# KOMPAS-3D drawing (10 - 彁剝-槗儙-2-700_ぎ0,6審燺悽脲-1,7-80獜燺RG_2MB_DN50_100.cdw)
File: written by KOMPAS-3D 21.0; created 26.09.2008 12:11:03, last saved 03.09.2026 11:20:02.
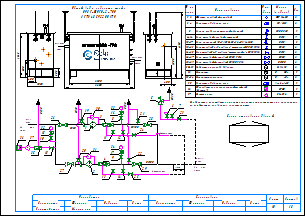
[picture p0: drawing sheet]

Sheets 1-2: A3, landscape

Document properties: Наименование: Макро:21; Автор: RaskoAdmin; Форматы листов документа: 2xA3; Полное имя файла: \\UR38nt01\Departments\КТО\КБ ПУРДГ\Заявки\Прайс-лист на типовые шкафы ГРПШ\ПРДГ_стандарт_20_03_2026\ПРДГ с RG_2MB\ПРДГ-ШУГО-2-700_до0,6МПа_Рвых-1,7-80кПа_RG_2MB_DN50_100.cdw

Title block, sheet 1: Наименование: Пункт учета газа / ПУГ-Ш-400-Р / ЛГТИ.485922.001ТУ; designation: ЛГТИ.03.4411141; sheet number: 1; Количество листов документа: 2; organisation: ООО "ЭЛЬСТЕР Газэлектроника"; Форматы листов документа: A3; stored path: C:\Рабочие документы\Компас\ПУГ\Схема.cdw; Разработал: Устинов; Проверил: Кошкин; Утвердил: Кошкин
Title block, sheet 2: sheet number: 2; stored path: D:\Рабочие документы\Заявки\ПУРДГ\ПУРДГ-ШУЭО-2-100-Р 4411220.cdw; designation, second copy: ЛГТИ.03.4411141-

Views: Вид 1, Вид 2
Referenced files: wcvoit.frw
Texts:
  Normal
  Вход
  газа
  PDI
  Выход
  Р=     кПа
  DN100
  DN50
  DN20
  Импульс DN20
  ≥5DN
  HYSWLongFangSong
  Общий вид и габариты шкафа
  ПРДГ-ШУГО-2-700
  Выход газа
  Вход газа
  Р=        МПа
  logo-rasko-ge.png
  № на
  схеме
  Усл.
  обозн.
  Марка
  (модель)
  Кол.
  Фильтр газовый фланцевый
  ФГ 16-50
  Регулятор давления газа
  RG/2MB
  Клапан предохранительный сбросной
  КПС DN20
  Кран шаровой газовый латунный
  DN15
  Кран кнопочный VE-РАСКО-НЗ-1,6-G1/2-М20
  Кран шаровой "под приварку" штуцерный DN20 PN16
  Кран шаровой "под приварку" штуцерный п/п DN15 PN16
  Кран шаровой фланцевый DN50 PN16
  Кран шаровой фланцевый DN100 PN16
  Индикатор перепада давления
  Delta 15
  Манометр
  Манометр-напоромер
  0...     МПа
  0...     кПа
  Обогреватель газогорелочный шкафной
  (Эльтон")
  Счетчик газа
  Venio-A-15
  ОГШН
  BK-G1,6
  Схема открывания дверей
  Предприятие изготовитель может заменять комплектующие на аналогичные,
  не ухудшающие заявленных характеристик.
  Должность
  Конструктор
  Фамилия
  Подпись
  Дата
  Согласовано
  Максимкин
  Лист
  Листов
  POLYLINE_STYLE_0.18_RGB_0_0_0
  POLYLINE_STYLE_0.50_RGB_0_0_0
  POLYLINE_STYLE_0.34_RGB_0_0_0
  PHANTOM_RGB_0_0_0_SC_1_THICK_0.18
  K5LT_THIN_RGB_0_0_0_THICK_0.18
  K5LT32769_RGB_0_0_0_THICK_0.18
  K5LT12_RGB_0_0_0_SC_1_THICK_0.18
  K5LT_DASHED_RGB_0_0_0_SC_1_THICK_0.18
  ACISOTGL_RGB_0_0_0_SC_0.8_THICK_0.25
  CONTINUOUS_RGB_0_127_31_THICK_0.3
  CONTINUOUS_RGB_0_0_255_THICK_0.35
  CONTINUOUS_RGB_255_0_0_THICK_0.35
  POLYLINE_STYLE_0.25_RGB_0_0_0
  CONTINUOUS_RGB_0_0_0_THICK_0.5
  POLYLINE_STYLE_0.35_RGB_0_0_255
  CONTINUOUS_RGB_0_0_0_THICK_0.4
  CONTINUOUS_RGB_0_0_0_THICK_0.35
  Без оформления
Dimensions and other numbers on the sheet: 1; 2; 3; 4; 5; 10; 27; 28; 29; 23; 8; 12; 19; 20; 21; 22; 25; 24; 30; 31; 15; 16; 26; 6; 7; 11; 14; 13; 33; 400; 1050; 500; 305; 2300; 1565; 32; 2600; 9; 17; 34; 1000; 4130; 1, 2; 3, 4; 6-14; 15-17; 18-23; 24-25; 26-27; 28-29; 30-31; 33-34; 35; 36; 37; 18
